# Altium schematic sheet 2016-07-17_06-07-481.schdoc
size 231 x 111 mm; SheetNumber: 1; SheetTotal: 1
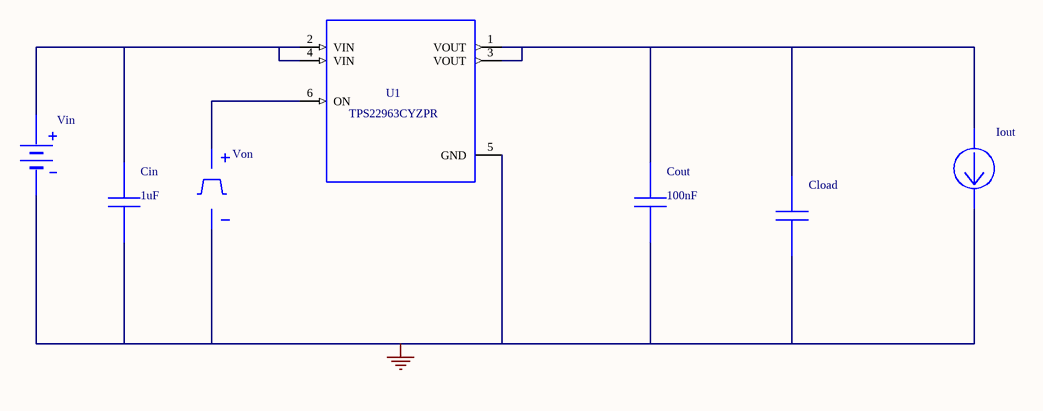
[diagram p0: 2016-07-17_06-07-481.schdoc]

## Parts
Cin  value 1uF  (hidden comment: C0603C105Z9VACTU)
Cload  GRM21BR71E104KA01L  (value not drawn)
Cout  value 100nF  (hidden comment: GRM155R60J104KA01D)
Iout  WB_CURRENT_LOAD  (value not drawn)
U1  TPS22963CYZPR
Vin  WB_BATTERY  (value not drawn)
Von  WB_PRIM_PWL_VOLTAGE_SOURCE  (value not drawn)

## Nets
0: Cin.2 Cload.2 Cout.2 Iout.2(-) U1.5(GND) Vin.2(-) Von.2(-)
NetCin_1: Cin.1 U1.2(VIN) U1.4(VIN) Vin.1(+)
NetCload_1: Cload.1 Cout.1 Iout.1(+) U1.1(VOUT) U1.3(VOUT)
NetU1_6: U1.6(ON) Von.1(+)

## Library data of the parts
Cin = C0603C105Z9VACTU: Manufacturer Name: Kemet
Cload = GRM21BR71E104KA01L: WB_PRIMITIVE_CAP; Manufacturer Name: WB_PRIMITIVE_CAPACITOR
Cout = GRM155R60J104KA01D: GRM155R60J104KA0; Manufacturer Name: MuRata
U1 = TPS22963CYZPR: Manufacturer Name: Texas Instruments
Von = WB_PRIM_PWL_VOLTAGE_SOURCE: WB_PRIM_PWL_VOLT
